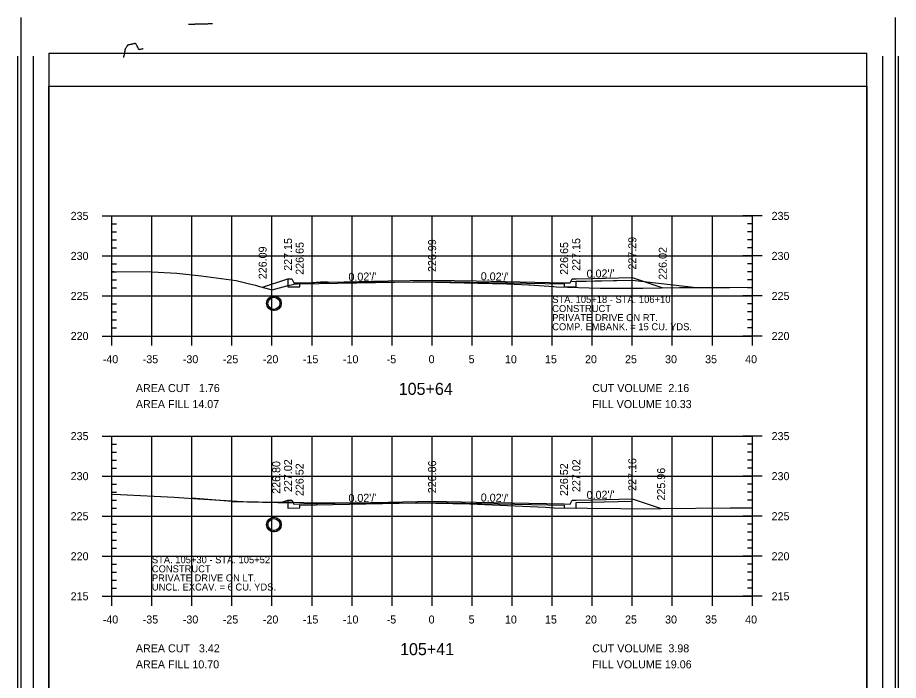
# Model space of a CAD drawing. Extents: x 1367903 to 1373764, y 376865 to 382130.
# Drawn here: x 1370927.2 to 1371147.2, y 377454.8 to 377620.4 of the extents above; entities that cross this region are included whole.
import ezdxf

# ---------------------------------------------------------------- set-up
doc = ezdxf.new("R2010")
doc.units = 0
for name, color, linetype in [('R_Axis', 7, 'Continuous'), ('R_Axis Annot', 7, 'Continuous'), ('R_Border', 7, 'Continuous'), ('R_Border PE', 7, 'Continuous'), ('R_Draft', 7, 'Continuous'), ('R_Drive', 7, 'Continuous'), ('R_Exist Surface', 7, 'Continuous'), ('R_Fin Surface', 7, 'Continuous'), ('R_Fin Surface Annot', 7, 'Continuous'), ('R_Grid', 7, 'Continuous'), ('R_Water', 7, 'Continuous')]:
    doc.layers.add(name, color=color, linetype=linetype)

msp = doc.modelspace()

# ---------------------------------------------------------------- linework, layer by layer
for points in [[(1370994.75, 377555.13), (1370994.75, 377554.46), (1370994.75, 377554.46), (1370994.75, 377553.1), (1370997.75, 377553.16), (1370997.75, 377553.83), (1371030.75, 377554.49), (1371063.75, 377553.83), (1371063.75, 377553.16), (1371066.75, 377553.1), (1371066.75, 377554.54), (1371080.75, 377554.82), (1371080.75, 377555.41)], [(1370994.75, 377499.87), (1370994.75, 377499.2), (1370994.75, 377499.2), (1370994.75, 377497.84), (1370997.75, 377497.9), (1370997.75, 377498.57), (1371030.75, 377499.23), (1371063.75, 377498.57), (1371063.75, 377497.9), (1371066.75, 377497.84), (1371066.75, 377499.28), (1371080.75, 377499.56), (1371080.75, 377500.15)]]:
    msp.add_lwpolyline(points)
at = {"layer": 'R_Axis'}
for p, q in [((1370948.35, 377570.84), (1370953.15, 377570.84)), ((1370950.75, 377540.84), (1370950.75, 377570.84)), ((1371113.15, 377570.84), (1371108.35, 377570.84)), ((1371110.75, 377540.84), (1371110.75, 377570.84)), ((1370950.75, 377568.84), (1370951.95, 377568.84)), ((1370950.75, 377566.84), (1370951.95, 377566.84)), ((1371110.75, 377568.84), (1371109.55, 377568.84)), ((1371110.75, 377566.84), (1371109.55, 377566.84)), ((1370950.75, 377564.84), (1370951.95, 377564.84)), ((1371110.75, 377564.84), (1371109.55, 377564.84)), ((1370950.75, 377562.84), (1370951.95, 377562.84)), ((1371110.75, 377562.84), (1371109.55, 377562.84)), ((1370948.35, 377560.84), (1370953.15, 377560.84)), ((1371113.15, 377560.84), (1371108.35, 377560.84)), ((1370950.75, 377558.84), (1370951.95, 377558.84)), ((1371110.75, 377558.84), (1371109.55, 377558.84)), ((1370950.75, 377556.84), (1370951.95, 377556.84)), ((1371110.75, 377556.84), (1371109.55, 377556.84)), ((1370950.75, 377554.84), (1370951.95, 377554.84)), ((1371110.75, 377554.84), (1371109.55, 377554.84)), ((1370950.75, 377552.84), (1370951.95, 377552.84)), ((1371110.75, 377552.84), (1371109.55, 377552.84)), ((1370948.35, 377550.84), (1370953.15, 377550.84)), ((1371113.15, 377550.84), (1371108.35, 377550.84)), ((1370950.75, 377548.84), (1370951.95, 377548.84)), ((1371110.75, 377548.84), (1371109.55, 377548.84)), ((1370950.75, 377546.84), (1370951.95, 377546.84)), ((1370950.75, 377544.84), (1370951.95, 377544.84)), ((1371110.75, 377546.84), (1371109.55, 377546.84)), ((1371110.75, 377544.84), (1371109.55, 377544.84)), ((1370950.75, 377538.44), (1370950.75, 377543.24)), ((1370950.75, 377542.84), (1370951.95, 377542.84)), ((1370960.75, 377538.44), (1370960.75, 377543.24)), ((1370970.75, 377538.44), (1370970.75, 377543.24)), ((1370980.75, 377538.44), (1370980.75, 377543.24)), ((1370990.75, 377538.44), (1370990.75, 377543.24)), ((1371000.75, 377538.44), (1371000.75, 377543.24)), ((1371010.75, 377538.44), (1371010.75, 377543.24)), ((1371020.75, 377538.44), (1371020.75, 377543.24)), ((1371030.75, 377538.44), (1371030.75, 377543.24)), ((1371040.75, 377538.44), (1371040.75, 377543.24)), ((1371050.75, 377538.44), (1371050.75, 377543.24)), ((1371060.75, 377538.44), (1371060.75, 377543.24)), ((1371070.75, 377538.44), (1371070.75, 377543.24)), ((1371080.75, 377538.44), (1371080.75, 377543.24)), ((1371090.75, 377538.44), (1371090.75, 377543.24)), ((1371100.75, 377538.44), (1371100.75, 377543.24)), ((1371110.75, 377542.84), (1371109.55, 377542.84)), ((1371110.75, 377538.44), (1371110.75, 377543.24)), ((1370948.35, 377540.84), (1370953.15, 377540.84)), ((1370950.75, 377540.84), (1371110.75, 377540.84)), ((1371113.15, 377540.84), (1371108.35, 377540.84)), ((1370948.35, 377515.84), (1370953.15, 377515.84)), ((1370950.75, 377475.84), (1370950.75, 377515.84)), ((1371113.15, 377515.84), (1371108.35, 377515.84)), ((1371110.75, 377475.84), (1371110.75, 377515.84)), ((1370950.75, 377513.84), (1370951.95, 377513.84)), ((1370950.75, 377511.84), (1370951.95, 377511.84)), ((1371110.75, 377513.84), (1371109.55, 377513.84)), ((1371110.75, 377511.84), (1371109.55, 377511.84)), ((1370950.75, 377509.84), (1370951.95, 377509.84)), ((1371110.75, 377509.84), (1371109.55, 377509.84)), ((1370950.75, 377507.84), (1370951.95, 377507.84)), ((1371110.75, 377507.84), (1371109.55, 377507.84)), ((1370948.35, 377505.84), (1370953.15, 377505.84)), ((1371113.15, 377505.84), (1371108.35, 377505.84)), ((1370950.75, 377503.84), (1370951.95, 377503.84)), ((1371110.75, 377503.84), (1371109.55, 377503.84)), ((1370950.75, 377501.84), (1370951.95, 377501.84)), ((1371110.75, 377501.84), (1371109.55, 377501.84)), ((1370950.75, 377499.84), (1370951.95, 377499.84)), ((1371110.75, 377499.84), (1371109.55, 377499.84)), ((1370950.75, 377497.84), (1370951.95, 377497.84)), ((1371110.75, 377497.84), (1371109.55, 377497.84)), ((1370948.35, 377495.84), (1370953.15, 377495.84)), ((1371113.15, 377495.84), (1371108.35, 377495.84)), ((1370950.75, 377493.84), (1370951.95, 377493.84)), ((1371110.75, 377493.84), (1371109.55, 377493.84)), ((1370950.75, 377491.84), (1370951.95, 377491.84)), ((1370950.75, 377489.84), (1370951.95, 377489.84)), ((1371110.75, 377491.84), (1371109.55, 377491.84)), ((1371110.75, 377489.84), (1371109.55, 377489.84)), ((1370950.75, 377487.84), (1370951.95, 377487.84)), ((1371110.75, 377487.84), (1371109.55, 377487.84)), ((1370948.35, 377485.84), (1370953.15, 377485.84)), ((1371113.15, 377485.84), (1371108.35, 377485.84)), ((1370950.75, 377483.84), (1370951.95, 377483.84)), ((1371110.75, 377483.84), (1371109.55, 377483.84)), ((1370950.75, 377481.84), (1370951.95, 377481.84)), ((1371110.75, 377481.84), (1371109.55, 377481.84)), ((1370950.75, 377479.84), (1370951.95, 377479.84)), ((1371110.75, 377479.84), (1371109.55, 377479.84)), ((1370950.75, 377473.44), (1370950.75, 377478.24)), ((1370950.75, 377477.84), (1370951.95, 377477.84)), ((1370960.75, 377473.44), (1370960.75, 377478.24)), ((1370970.75, 377473.44), (1370970.75, 377478.24)), ((1370980.75, 377473.44), (1370980.75, 377478.24)), ((1370990.75, 377473.44), (1370990.75, 377478.24)), ((1371000.75, 377473.44), (1371000.75, 377478.24)), ((1371010.75, 377473.44), (1371010.75, 377478.24)), ((1371020.75, 377473.44), (1371020.75, 377478.24)), ((1371030.75, 377473.44), (1371030.75, 377478.24)), ((1371040.75, 377473.44), (1371040.75, 377478.24)), ((1371050.75, 377473.44), (1371050.75, 377478.24)), ((1371060.75, 377473.44), (1371060.75, 377478.24)), ((1371070.75, 377473.44), (1371070.75, 377478.24)), ((1371080.75, 377473.44), (1371080.75, 377478.24)), ((1371090.75, 377473.44), (1371090.75, 377478.24)), ((1371100.75, 377473.44), (1371100.75, 377478.24)), ((1371110.75, 377477.84), (1371109.55, 377477.84)), ((1371110.75, 377473.44), (1371110.75, 377478.24)), ((1370948.35, 377475.84), (1370953.15, 377475.84)), ((1370950.75, 377475.84), (1371110.75, 377475.84)), ((1371113.15, 377475.84), (1371108.35, 377475.84))]:
    msp.add_line(p, q, dxfattribs=at)
at = {"layer": 'R_Border'}
for p, q in [((1370928.02, 377620.35), (1370928.02, 377279.12)), ((1371146.41, 377620.35), (1371146.41, 377279.12)), ((1370935.05, 377611.47), (1371139.37, 377611.47)), ((1370935.05, 377611.47), (1370935.05, 377280.59)), ((1371139.37, 377280.59), (1371139.37, 377611.47))]:
    msp.add_line(p, q, dxfattribs=at)
at = {"layer": 'R_Border PE'}
for p, q in [((1370927.22, 377610.76), (1370927.22, 377288.8)), ((1370931.13, 377610.76), (1370931.13, 377288.8)), ((1371143.3, 377288.8), (1371143.3, 377610.76)), ((1371147.22, 377288.8), (1371147.22, 377610.76)), ((1370935.05, 377603.25), (1371139.37, 377603.25)), ((1370935.05, 377288.8), (1370935.05, 377603.25)), ((1371139.37, 377603.25), (1371139.37, 377288.8))]:
    msp.add_line(p, q, dxfattribs=at)
for points in [[(1370971.91, 377618.69), (1370971.85, 377618.69), (1370971.58, 377618.68), (1370971.45, 377618.68), (1370971.38, 377618.67), (1370971.22, 377618.67), (1370970.86, 377618.66), (1370970.53, 377618.65), (1370969.9, 377618.63)], [(1370972.36, 377618.7), (1370971.91, 377618.69)], [(1370975.92, 377618.79), (1370975.58, 377618.78), (1370975.38, 377618.78), (1370975.22, 377618.77), (1370974.99, 377618.76), (1370974.83, 377618.76), (1370974.64, 377618.75), (1370974.39, 377618.75), (1370974.2, 377618.74), (1370973.92, 377618.73), (1370973.82, 377618.73), (1370973.77, 377618.73), (1370973.55, 377618.72), (1370973.44, 377618.72), (1370973.22, 377618.71), (1370973.14, 377618.72), (1370972.72, 377618.7), (1370972.47, 377618.7), (1370972.36, 377618.7)], [(1370958.61, 377612.54), (1370958.59, 377612.55), (1370958.57, 377612.55), (1370958.55, 377612.55), (1370958.53, 377612.55), (1370958.5, 377612.55), (1370958.47, 377612.55), (1370958.45, 377612.55), (1370958.31, 377612.51), (1370958.19, 377612.48), (1370957.92, 377612.41), (1370957.7, 377612.36), (1370957.68, 377612.35), (1370957.66, 377612.35), (1370957.63, 377612.34), (1370957.62, 377612.34), (1370957.61, 377612.35), (1370957.59, 377612.35), (1370957.57, 377612.36), (1370957.54, 377612.38), (1370957.52, 377612.39), (1370957.5, 377612.4), (1370957.49, 377612.42), (1370957.47, 377612.45), (1370957.46, 377612.47), (1370957.44, 377612.5), (1370957.42, 377612.55), (1370957.32, 377612.76), (1370957.21, 377613), (1370957.11, 377613.23), (1370957.1, 377613.26), (1370957.09, 377613.28), (1370957.05, 377613.34), (1370957.02, 377613.39), (1370956.9, 377613.57), (1370956.82, 377613.69), (1370956.79, 377613.74), (1370956.77, 377613.76), (1370956.76, 377613.78), (1370956.73, 377613.81), (1370956.72, 377613.83), (1370956.7, 377613.84), (1370956.69, 377613.85), (1370956.66, 377613.87), (1370956.65, 377613.87), (1370956.62, 377613.88), (1370956.59, 377613.88), (1370956.58, 377613.88), (1370956.54, 377613.88), (1370956.43, 377613.86), (1370956.26, 377613.82), (1370956.07, 377613.77), (1370955.92, 377613.74), (1370955.82, 377613.72), (1370955.68, 377613.69), (1370955.56, 377613.66), (1370955.38, 377613.63), (1370955.16, 377613.58), (1370955.11, 377613.57), (1370954.99, 377613.54), (1370954.88, 377613.52), (1370954.84, 377613.51), (1370954.81, 377613.5), (1370954.79, 377613.5), (1370954.77, 377613.49), (1370954.76, 377613.49), (1370954.74, 377613.47), (1370954.72, 377613.46), (1370954.7, 377613.44), (1370954.67, 377613.42), (1370954.64, 377613.39), (1370954.62, 377613.35), (1370954.59, 377613.31), (1370954.55, 377613.26), (1370954.49, 377613.16), (1370954.39, 377613.02), (1370954.31, 377612.89), (1370954.22, 377612.75), (1370954.17, 377612.67), (1370954.13, 377612.62), (1370954.09, 377612.55), (1370954.08, 377612.54), (1370954.07, 377612.52), (1370954.06, 377612.5), (1370954.06, 377612.48), (1370954.05, 377612.46), (1370954.05, 377612.44), (1370954.04, 377612.42), (1370954.03, 377612.39), (1370954.03, 377612.37), (1370954.02, 377612.35), (1370954.02, 377612.33), (1370954, 377612.24), (1370953.96, 377612), (1370953.92, 377611.76), (1370953.9, 377611.65), (1370953.81, 377611.18), (1370953.79, 377611.04), (1370953.75, 377610.84), (1370953.69, 377610.54), (1370953.66, 377610.39)]]:
    msp.add_lwpolyline(points, dxfattribs=at)
at = {"layer": 'R_Drive'}
for p, q in [((1371065.41, 377554.46), (1371080.74, 377554.77)), ((1371080.74, 377554.77), (1371096.75, 377552.95)), ((1370980.75, 377499.5), (1370970.75, 377500.31)), ((1370980.75, 377499.5), (1370996.08, 377499.19))]:
    msp.add_line(p, q, dxfattribs=at)
at = {"layer": 'R_Exist Surface'}
for points in [[(1370950.75, 377556.95), (1370951.28, 377556.92), (1370960.76, 377556.86), (1370967.02, 377556.54), (1370973.1, 377555.84), (1370981.84, 377554.68), (1370985.12, 377553.91), (1370986.6, 377553.51), (1370987.66, 377553.24), (1370990.8, 377552.33), (1370994.46, 377553.36), (1370996.18, 377553.78), (1371001.75, 377554.26), (1371002.84, 377554.33), (1371004.65, 377554.34), (1371031.61, 377554.3), (1371049.42, 377553.83), (1371054.87, 377553.66), (1371055.13, 377553.66), (1371061.06, 377553.2), (1371061.07, 377553.2), (1371061.12, 377553.2), (1371061.83, 377553.14), (1371072.75, 377552.76), (1371077.85, 377552.77), (1371083.42, 377552.82), (1371092.52, 377552.93), (1371097.21, 377552.96), (1371105, 377552.97), (1371110.75, 377553.03)], [(1370950.75, 377501.37), (1370952.88, 377501.28), (1370966.34, 377500.61), (1370972.35, 377500.21), (1370979.32, 377499.72), (1370983.43, 377499.53), (1370991.35, 377499.34), (1370993.75, 377499.45), (1370998.69, 377499.26), (1371002.99, 377499.21), (1371015.81, 377499.15), (1371031.65, 377499.11), (1371040.19, 377498.92), (1371057.12, 377498.19), (1371059.04, 377498.11), (1371061.24, 377497.92), (1371077.92, 377497.75), (1371083.64, 377497.69), (1371088, 377497.75), (1371105.23, 377497.96), (1371107.53, 377497.89), (1371110.75, 377497.94)]]:
    msp.add_lwpolyline(points, dxfattribs=at)
at = {"layer": 'R_Fin Surface'}
for points in [[(1370988.42, 377553.02), (1370994.75, 377555.13), (1370995.75, 377555.13), (1370996.25, 377554.13), (1370997.75, 377554.16), (1371019.75, 377554.6), (1371030.75, 377554.82), (1371041.75, 377554.6), (1371063.75, 377554.16), (1371065.25, 377554.13), (1371065.75, 377555.13), (1371066.75, 377555.13), (1371070.75, 377555.21), (1371080.75, 377555.41), (1371088.35, 377552.88)], [(1370993.44, 377499.43), (1370994.75, 377499.87), (1370995.75, 377499.87), (1370996.25, 377498.87), (1370997.75, 377498.9), (1371019.75, 377499.34), (1371030.75, 377499.56), (1371041.75, 377499.34), (1371063.75, 377498.9), (1371065.25, 377498.87), (1371065.75, 377499.87), (1371066.75, 377499.87), (1371070.75, 377499.95), (1371080.75, 377500.15), (1371087.96, 377497.75)]]:
    msp.add_lwpolyline(points, dxfattribs=at)
at = {"layer": 'R_Grid'}
for p, q in [((1370950.75, 377570.84), (1371110.75, 377570.84)), ((1370950.75, 377540.84), (1370950.75, 377570.84)), ((1370960.75, 377540.84), (1370960.75, 377570.84)), ((1370970.75, 377540.84), (1370970.75, 377570.84)), ((1370980.75, 377540.84), (1370980.75, 377570.84)), ((1370990.75, 377540.84), (1370990.75, 377570.84)), ((1371000.75, 377540.84), (1371000.75, 377570.84)), ((1371010.75, 377540.84), (1371010.75, 377570.84)), ((1371020.75, 377540.84), (1371020.75, 377570.84)), ((1371030.75, 377540.84), (1371030.75, 377570.84)), ((1371040.75, 377540.84), (1371040.75, 377570.84)), ((1371050.75, 377540.84), (1371050.75, 377570.84)), ((1371060.75, 377540.84), (1371060.75, 377570.84)), ((1371070.75, 377540.84), (1371070.75, 377570.84)), ((1371080.75, 377540.84), (1371080.75, 377570.84)), ((1371090.75, 377540.84), (1371090.75, 377570.84)), ((1371100.75, 377540.84), (1371100.75, 377570.84)), ((1371110.75, 377540.84), (1371110.75, 377570.84)), ((1370950.75, 377560.84), (1371110.75, 377560.84)), ((1370950.75, 377550.84), (1371110.75, 377550.84)), ((1370950.75, 377540.84), (1371110.75, 377540.84)), ((1370950.75, 377515.84), (1371110.75, 377515.84)), ((1370950.75, 377475.84), (1370950.75, 377515.84)), ((1370960.75, 377475.84), (1370960.75, 377515.84)), ((1370970.75, 377475.84), (1370970.75, 377515.84)), ((1370980.75, 377475.84), (1370980.75, 377515.84)), ((1370990.75, 377475.84), (1370990.75, 377515.84)), ((1371000.75, 377475.84), (1371000.75, 377515.84)), ((1371010.75, 377475.84), (1371010.75, 377515.84)), ((1371020.75, 377475.84), (1371020.75, 377515.84)), ((1371030.75, 377475.84), (1371030.75, 377515.84)), ((1371040.75, 377475.84), (1371040.75, 377515.84)), ((1371050.75, 377475.84), (1371050.75, 377515.84)), ((1371060.75, 377475.84), (1371060.75, 377515.84)), ((1371070.75, 377475.84), (1371070.75, 377515.84)), ((1371080.75, 377475.84), (1371080.75, 377515.84)), ((1371090.75, 377475.84), (1371090.75, 377515.84)), ((1371100.75, 377475.84), (1371100.75, 377515.84)), ((1371110.75, 377475.84), (1371110.75, 377515.84)), ((1370950.75, 377505.84), (1371110.75, 377505.84)), ((1370950.75, 377495.84), (1371110.75, 377495.84)), ((1370950.75, 377485.84), (1371110.75, 377485.84)), ((1370950.75, 377475.84), (1371110.75, 377475.84))]:
    msp.add_line(p, q, dxfattribs=at)
at = {"layer": 'R_Water'}
for p, q in [((1370991.25, 377550.86), (1370991.25, 377550.81)), ((1370991.25, 377550.52), (1370991.25, 377550.48)), ((1370991.25, 377547.52), (1370991.25, 377547.48)), ((1370991.25, 377547.19), (1370991.25, 377547.14)), ((1370991.25, 377495.59), (1370991.25, 377495.54)), ((1370991.25, 377495.25), (1370991.25, 377495.2)), ((1370991.25, 377492.25), (1370991.25, 377492.2)), ((1370991.25, 377491.92), (1370991.25, 377491.87))]:
    msp.add_line(p, q, dxfattribs=at)
for centre, radius in [((1370991.25, 377549), 1.83), ((1370991.25, 377549), 1.5), ((1370991.25, 377493.73), 1.83), ((1370991.25, 377493.73), 1.5)]:
    msp.add_circle(centre, radius, dxfattribs=at)

# ---------------------------------------------------------------- texts
at = {"layer": 'R_Axis Annot'}
for s, height, p in [('235', 2, (1370940.46, 377569.84)), ('235', 2, (1371115.55, 377569.84)), ('230', 2, (1370940.47, 377559.84)), ('230', 2, (1371115.55, 377559.84)), ('225', 2, (1370940.46, 377549.84)), ('225', 2, (1371115.55, 377549.84)), ('220', 2, (1370940.47, 377539.84)), ('220', 2, (1371115.55, 377539.84)), ('-40', 2, (1370948.48, 377534.04)), ('-35', 2, (1370958.47, 377534.04)), ('-30', 2, (1370968.48, 377534.04)), ('-25', 2, (1370978.47, 377534.04)), ('-20', 2, (1370988.48, 377534.04)), ('-15', 2, (1370998.47, 377534.04)), ('-10', 2, (1371008.48, 377534.04)), ('-5', 2, (1371019.41, 377534.04)), ('0', 2, (1371029.87, 377534.04)), ('5', 2, (1371039.87, 377534.04)), ('10', 2, (1371048.94, 377534.04)), ('15', 2, (1371058.94, 377534.04)), ('20', 2, (1371068.94, 377534.04)), ('25', 2, (1371078.94, 377534.04)), ('30', 2, (1371088.94, 377534.04)), ('35', 2, (1371098.94, 377534.04)), ('40', 2, (1371108.94, 377534.04)), ('AREA CUT   1.76', 2, (1370956.75, 377526.84)), ('105+64', 3, (1371022.41, 377526.14)), ('CUT VOLUME  2.16', 2, (1371070.75, 377526.84)), ('AREA FILL 14.07', 2, (1370956.75, 377522.84)), ('FILL VOLUME 10.33', 2, (1371070.75, 377522.84)), ('235', 2, (1370940.46, 377514.84)), ('235', 2, (1371115.55, 377514.84)), ('230', 2, (1370940.47, 377504.84)), ('230', 2, (1371115.55, 377504.84)), ('225', 2, (1370940.46, 377494.84)), ('225', 2, (1371115.55, 377494.84)), ('220', 2, (1370940.47, 377484.84)), ('220', 2, (1371115.55, 377484.84)), ('215', 2, (1370940.46, 377474.84)), ('215', 2, (1371115.55, 377474.84)), ('-40', 2, (1370948.48, 377469.04)), ('-35', 2, (1370958.47, 377469.04)), ('-30', 2, (1370968.48, 377469.04)), ('-25', 2, (1370978.47, 377469.04)), ('-20', 2, (1370988.48, 377469.04)), ('-15', 2, (1370998.47, 377469.04)), ('-10', 2, (1371008.48, 377469.04)), ('-5', 2, (1371019.41, 377469.04)), ('0', 2, (1371029.87, 377469.04)), ('5', 2, (1371039.87, 377469.04)), ('10', 2, (1371048.94, 377469.04)), ('15', 2, (1371058.94, 377469.04)), ('20', 2, (1371068.94, 377469.04)), ('25', 2, (1371078.94, 377469.04)), ('30', 2, (1371088.94, 377469.04)), ('35', 2, (1371098.94, 377469.04)), ('40', 2, (1371108.94, 377469.04)), ('AREA CUT   3.42', 2, (1370956.75, 377461.84)), ('105+41', 3, (1371022.74, 377461.14)), ('CUT VOLUME  3.98', 2, (1371070.75, 377461.84)), ('AREA FILL 10.70', 2, (1370956.75, 377457.84)), ('FILL VOLUME 19.06', 2, (1371070.75, 377457.84))]:
    msp.add_text(s, height=height, dxfattribs=at).set_placement(p)
at = {"layer": 'R_Draft'}
for s, p in [('STA. 105+18 - STA. 106+10', (1371060.75, 377549.09)), ('CONSTRUCT', (1371060.75, 377546.82)), ('PRIVATE DRIVE ON RT.', (1371060.75, 377544.55)), ('COMP. EMBANK. = 15 CU. YDS.', (1371060.75, 377542.28)), ('STA. 105+30 - STA. 105+52', (1370960.75, 377484.09)), ('CONSTRUCT', (1370960.75, 377481.82)), ('PRIVATE DRIVE ON LT.', (1370960.75, 377479.55)), ('UNCL. EXCAV. = 6 CU. YDS.', (1370960.75, 377477.28))]:
    msp.add_text(s, height=1.75, dxfattribs=at).set_placement(p)
at = {"layer": 'R_Fin Surface Annot'}
for s, rotation, p in [('227.15', 90, (1370995.75, 377557.13)), ('226.99', 90, (1371031.75, 377556.82)), ('227.15', 90, (1371067.75, 377557.13)), ('227.29', 90, (1371081.75, 377557.41)), ('226.09', 90, (1370989.42, 377555.02)), ('226.65', 90, (1370998.67, 377556.13)), ('226.65', 90, (1371064.73, 377556.13)), ('226.02', 90, (1371089.35, 377554.88)), ("0.02'/'", 1.1458, (1371009.87, 377554.6)), ("0.02'/'", 358.8542, (1371042.88, 377554.78)), ("0.02'/'", 1.1458, (1371069.37, 377555.38)), ('227.02', 90, (1370995.75, 377501.87)), ('226.86', 90, (1371031.75, 377501.56)), ('227.02', 90, (1371067.75, 377501.87)), ('227.16', 90, (1371081.75, 377502.15)), ('226.80', 90, (1370992.82, 377501.43)), ('226.52', 90, (1370998.65, 377500.87)), ('226.52', 90, (1371064.69, 377500.87)), ('225.96', 90, (1371088.96, 377499.75)), ("0.02'/'", 1.1458, (1371009.87, 377499.34)), ("0.02'/'", 358.8542, (1371042.88, 377499.52)), ("0.02'/'", 1.1458, (1371069.37, 377500.12))]:
    msp.add_text(s, height=2, rotation=rotation, dxfattribs=at).set_placement(p)

doc.saveas('drawing.dxf')
